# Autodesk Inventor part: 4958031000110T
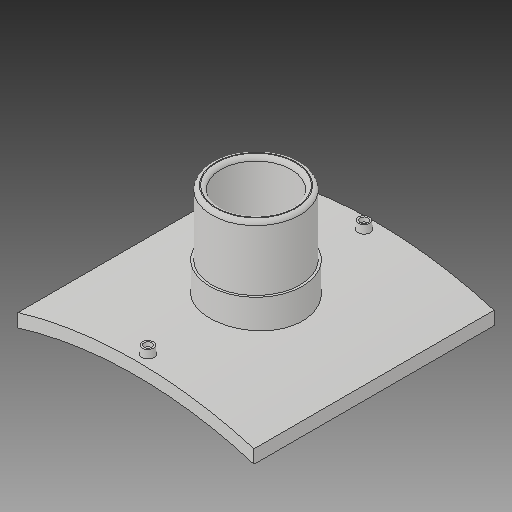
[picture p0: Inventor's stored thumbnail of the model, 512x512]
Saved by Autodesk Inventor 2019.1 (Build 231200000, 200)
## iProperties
Created: 2017-10
Part Number: 4958031000110T
Material: Generic
Description: PLASSON BRANCH SADDLE  1000x110
Document SubType Name: Modeling
Designer: KIM
Mass: 2754.05 g
Surface Area: 3037.44 cm^2
Volume: 2754.05 cm^3
Density: 1 g/cm^3
Appearance: Default
Author: KIM
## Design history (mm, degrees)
derived "495803.ipt"
feature "Solid1::495803.ipt"
tag "TaggingFeature1"
body "Solid1"
other parameters: "d1" = 16, "d2" = 295, "d4" = 0, "d12" = 525.6, "d13" = 14, "d14" = 135, "d16" = 5 deg, "d18" = 4, "d19" = 14, "d20" = 0, "d21" = 3, "d22" = 0, "d23" = 631, "d24" = 115.5, "d25" = 16, "d26" = 88, "d28" = 0, "d29" = 9.6, "d31" = 0, "d32" = 57.5, "d33" = 0, "d37" = 80.5, "d38" = 0, "d39" = 5, "B_" = 295, "H_" = 115, "x_" = 16, "D_" = 16
